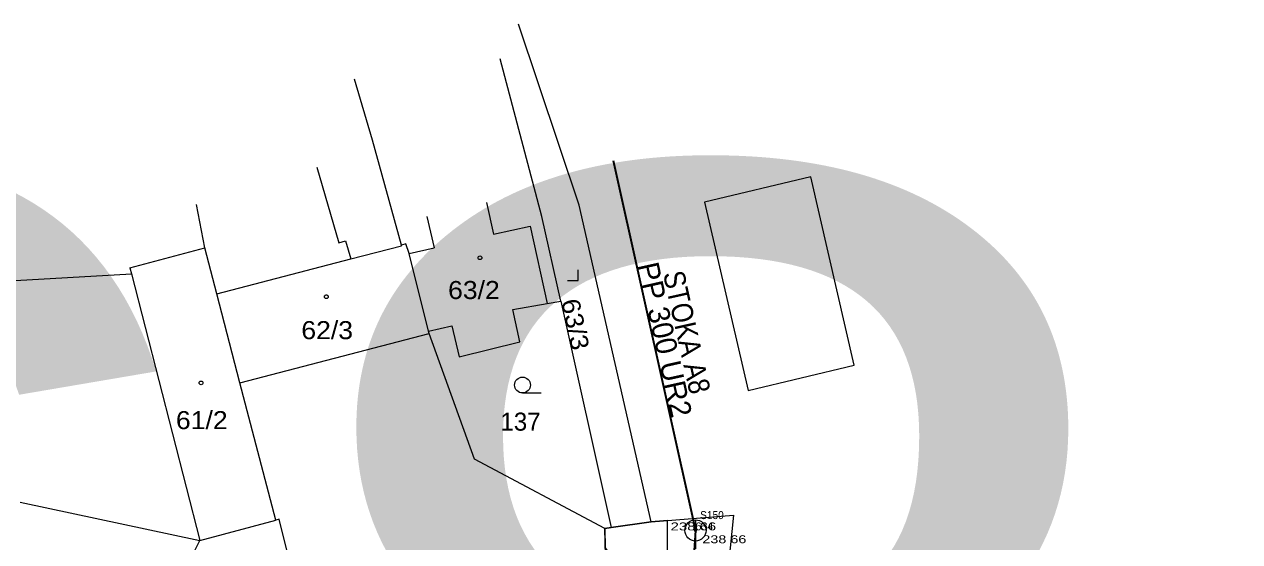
# Model space of a CAD drawing. Extents: x -686207 to -681951, y -1020493 to -1017811.
# Drawn here: x -682393.2 to -682278.7, y -1018844.9 to -1018796.2 of the extents above; entities that cross this region are included whole.
import ezdxf
from ezdxf.enums import TextEntityAlignment as Align

# ---------------------------------------------------------------- set-up
doc = ezdxf.new("R2010")
doc.units = 0
doc.header["$LTSCALE"] = 0.4
doc.header["$PDMODE"] = 32
doc.header["$PDSIZE"] = 0.2
for name, color, linetype, lineweight in [('1', 7, 'Continuous', 13), ('10', 7, 'Continuous', 13), ('13', 7, 'Continuous', 13), ('23', 7, 'Continuous', 13), ('3', 7, 'Continuous', 13), ('4', 7, 'Continuous', 13), ('45', 7, 'Continuous', 35), ('5', 7, 'Continuous', 13)]:
    doc.layers.add(name, color=color, linetype=linetype, lineweight=lineweight)
doc.layers.add('15', color=7, linetype='Continuous')
doc.layers.add('2', color=7, linetype='Continuous')

msp = doc.modelspace()

# ---------------------------------------------------------------- linework, layer by layer
at = {"layer": '1'}
for p, q in [((-682342.67, -1018822.27), (-682337.91, -1018843.6)), ((-682393.58, -1018841.21), (-682376.65, -1018844.81)), ((-682326.39, -1018842.43), (-682326.88, -1018847.05)), ((-682376.65, -1018844.81), (-682369.51, -1018842.9)), ((-682338.53, -1018843.69), (-682337.91, -1018843.6)), ((-682338.36, -1018850.71), (-682338.53, -1018843.69))]:
    msp.add_line(p, q, dxfattribs=at)
for points in [[(-682334.14, -1018843.04), (-682340.95, -1018813.2), (-682346.65, -1018796.17)], [(-682342.67, -1018822.27), (-682344.45, -1018814.29), (-682348.38, -1018799.44)], [(-682357.68, -1018816.97), (-682360.4, -1018807.08), (-682362.1, -1018801.33)], [(-682375.05, -1018821.57), (-682376.18, -1018817.24), (-682376.97, -1018813.14)], [(-682375.05, -1018821.57), (-682362.45, -1018818.28), (-682357.67, -1018817.03), (-682357.68, -1018816.97)], [(-682355.13, -1018825.1), (-682356.96, -1018817.76), (-682357.25, -1018816.87), (-682357.68, -1018816.97)], [(-682369.51, -1018842.9), (-682372.88, -1018829.94), (-682375.05, -1018821.57)], [(-682355.13, -1018825.1), (-682352.94, -1018824.57), (-682352.23, -1018827.49), (-682346.53, -1018826.1), (-682347.17, -1018823.03), (-682343.94, -1018822.48), (-682342.67, -1018822.27)], [(-682338.53, -1018843.69), (-682350.79, -1018837.14), (-682355.07, -1018825.32), (-682355.13, -1018825.1)], [(-682362.72, -1018853.46), (-682367.32, -1018850.37), (-682369.2, -1018842.81), (-682369.51, -1018842.9)], [(-682337.91, -1018843.6), (-682334.14, -1018843.04), (-682326.39, -1018842.43)], [(-682384.87, -1018866.27), (-682381.31, -1018856.59), (-682379.86, -1018852.52), (-682377.26, -1018846), (-682376.65, -1018844.81)]]:
    msp.add_lwpolyline(points, dxfattribs=at)
msp.add_lwpolyline([(-682315.04, -1018828.29), (-682319.11, -1018810.53), (-682329.12, -1018812.92), (-682325.02, -1018830.68)], close=True, dxfattribs=at)
msp.add_point((-682329.98, -1018843.859), dxfattribs=at)
at = {"layer": '10'}
msp.add_line((-682329.98, -1018842.859), (-682329.98, -1018845.607), dxfattribs=at)
msp.add_circle((-682329.98, -1018843.86), 1.0002, dxfattribs=at)
at = {"layer": '13'}
msp.add_lwpolyline([(-682332.61, -1018842.92), (-682334.14, -1018843.04), (-682337.91, -1018843.6), (-682338.53, -1018843.69), (-682338.49, -1018845.51), (-682334.64, -1018850.84), (-682337.52, -1018877.62), (-682338.65, -1018881.19), (-682345.4, -1018888.98), (-682343.92, -1018890.32), (-682336.87, -1018882.19), (-682335.56, -1018878.04), (-682332.6, -1018850.62)], close=True, dxfattribs=at)
at = {"layer": '3'}
msp.add_line((-682346.273, -1018830.91), (-682344.523, -1018830.91), dxfattribs=at)
msp.add_lwpolyline([(-682342.041, -1018820.31), (-682341.04, -1018820.31), (-682341.04, -1018819.31)], dxfattribs=at)
msp.add_circle((-682346.2729, -1018830.1598), 0.75, dxfattribs=at)
at = {"layer": '4'}
for p, q in [((-682365.64, -1018809.63), (-682363.57, -1018816.76)), ((-682349.67, -1018812.96), (-682349.01, -1018815.95)), ((-682355.27, -1018814.27), (-682354.6, -1018817.24)), ((-682349.01, -1018815.95), (-682345.56, -1018815.18)), ((-682345.56, -1018815.18), (-682343.94, -1018822.48)), ((-682383.26, -1018819.11), (-682376.18, -1018817.24)), ((-682356.96, -1018817.76), (-682354.6, -1018817.24)), ((-682395.16, -1018820.39), (-682383.11, -1018819.69)), ((-682383.26, -1018819.11), (-682383.11, -1018819.69)), ((-682383.11, -1018819.69), (-682376.65, -1018844.81)), ((-682372.88, -1018829.94), (-682355.07, -1018825.32))]:
    msp.add_line(p, q, dxfattribs=at)
msp.add_lwpolyline([(-682363.57, -1018816.76), (-682362.94, -1018816.58), (-682362.45, -1018818.28)], dxfattribs=at)
at = {"layer": '45'}
for p, q in [((-682337.74, -1018809.018), (-682329.98, -1018843.859)), ((-682329.98, -1018843.859), (-682330.492, -1018851.835))]:
    msp.add_line(p, q, dxfattribs=at)
at = {"layer": '5'}
for centre in [(-682350.2768, -1018818.1692), (-682364.7468, -1018821.8392), (-682376.5468, -1018829.9592)]:
    msp.add_circle(centre, 0.175, dxfattribs=at)

# ---------------------------------------------------------------- texts
at = {"layer": '15'}
msp.add_text('PP 300 UR2', height=2, rotation=282.556, dxfattribs=at).set_placement((-682333.8415, -1018826.0986), align=Align.CENTER)
at = {"layer": '15', "width": 0.9}
msp.add_text('STOKA A8', height=2, rotation=282.556, dxfattribs=at).set_placement((-682331.7707, -1018825.4011), align=Align.CENTER)
at = {"layer": '15', "width": 0.95}
msp.add_text('S150', height=0.75, dxfattribs=at).set_placement((-682328.427, -1018842.794), align=Align.CENTER)
at = {"layer": '2', "width": 1.1}
for s, p in [('63/2', (-682353.281, -1018822.059)), ('62/3', (-682367.101, -1018825.84)), ('61/2', (-682378.911, -1018834.32))]:
    msp.add_text(s, height=1.7, dxfattribs=at).set_placement(p)
msp.add_text('63/3', height=1.7, rotation=282, dxfattribs=at).set_placement((-682342.627, -1018822.234))
at = {"layer": '2'}
for s, height, p in [('137', 1.7, (-682348.354, -1018834.46)), ('634', 0.75, (-682329.98, -1018843.85))]:
    msp.add_text(s, height=height, dxfattribs=at).set_placement(p)
at = {"layer": '23', "width": 1.15}
msp.add_text('681679', height=100, dxfattribs=at).set_placement((-682200.0295, -1018910), align=Align.CENTER)
at = {"layer": '3'}
for s, width, p in [('238 66 ', 1.4, (-682329.98, -1018843.859)), ('238 66', 1.35, (-682327.262, -1018845.069))]:
    msp.add_text(s, height=0.75, dxfattribs=dict(at, width=width)).set_placement(p, align=Align.CENTER)

doc.saveas('drawing.dxf')
